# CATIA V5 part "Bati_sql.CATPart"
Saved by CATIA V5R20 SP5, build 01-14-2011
Part number: Bati sql
Publications: "A", "Droite.1", "Droite.2"
Bounding box of the stored display mesh (mm): x -20 to 20, y 0 to 51, z 0 to 0
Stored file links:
  C:\Documents and Settings\pschann\Bureau\IAO\Bati_sql.CATPart
  C:\Documents and Settings\pschann\Bureau\IAO\Squelette.CATProduct
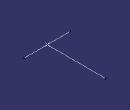
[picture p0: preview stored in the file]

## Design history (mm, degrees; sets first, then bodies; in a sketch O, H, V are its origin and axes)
External parameters (linked from other documents)
  External.BC = 41 mm
  External.AB = 10 mm
Set1
  Point1 "A": (0, 0, 0)
  Line1: type Normal, RefPoint Point1, RefSkin zx-plane, Start 0, End 51 {= External.BC +External.AB}
  Line2: type Normal, RefPoint Point1, RefSkin yz-plane, Start -20, End 20
Body1 (main body)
